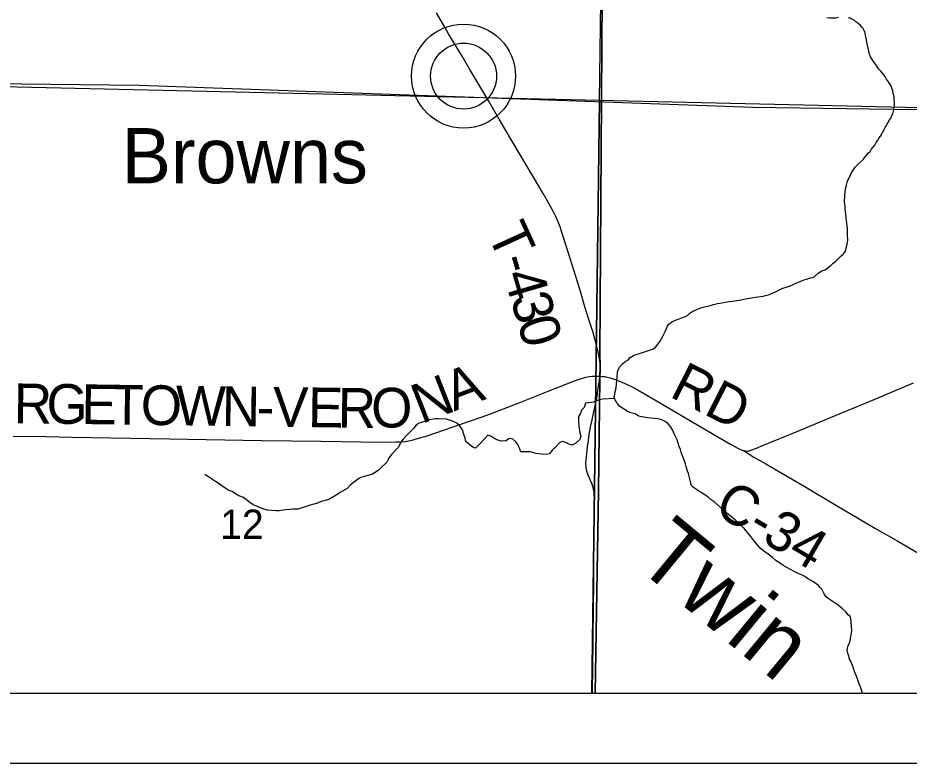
# Model space of a CAD drawing. Extents: x 0 to 1391, y -24 to 440.
# Drawn here: x 285.85 to 311.35, y 280 to 301.31 of the extents above; entities that cross this region are included whole.
import ezdxf

# ---------------------------------------------------------------- set-up
doc = ezdxf.new("R2010")
doc.units = 0
for name, color, linetype in [('GM_X_Corporation', 7, 'Continuous'), ('GM_X_County_Road', 7, 'Continuous'), ('GM_X_County_Road_Text', 7, 'Continuous'), ('GM_X_Major_River', 7, 'Continuous'), ('GM_X_Major_River_Text', 7, 'Continuous'), ('GM_X_Minor_River', 7, 'Continuous'), ('GM_X_Rail_Line', 7, 'Continuous'), ('GM_X_Section_Text', 7, 'Continuous'), ('GM_X_Township_Road', 7, 'Continuous'), ('GM_X_Township_Road_Text', 7, 'Continuous'), ('GM_X_Unincorporated', 7, 'Continuous'), ('GM_X_Unincorporated_Location', 7, 'Continuous'), ('GM_X_Unincorporated_Text', 7, 'Continuous'), ('SH_Data', 7, 'Continuous')]:
    doc.layers.add(name, color=color, linetype=linetype)

msp = doc.modelspace()

# ---------------------------------------------------------------- linework, layer by layer
at = {"layer": 'GM_X_Corporation'}
for points in [[(192, 321.564), (192, 282), (328, 282), (328, 319.315), (327.358, 319.321), (326.017, 319.331), (324.492, 319.344), (323.626, 319.346), (322.004, 319.36), (321.681, 319.364), (321.557, 319.363), (320.47, 319.355), (320.375, 319.355), (320.324, 319.361), (320.28, 319.374), (320.232, 319.401), (302.742, 319.575), (282.759, 319.815), (282.746, 319.815), (270.99, 319.899)], [(192, 321.564), (192, 282), (302.362, 282), (302.463, 287.791), (302.504, 290.987), (302.506, 291.392), (302.503, 291.694), (302.611, 309.266), (302.645, 314.81), (302.659, 314.843), (302.674, 314.915), (302.675, 315.033), (302.678, 315.834), (302.714, 317.94), (302.717, 318.152), (302.742, 319.575), (282.759, 319.815), (282.746, 319.815), (270.99, 319.899)], [(320.232, 319.401), (302.742, 319.575), (302.717, 318.152), (302.714, 317.94), (302.678, 315.834), (302.675, 315.033), (302.674, 314.915), (302.659, 314.843), (302.645, 314.81), (302.611, 309.266), (302.503, 291.694), (302.506, 291.392), (302.504, 290.987), (302.463, 287.791), (302.362, 282), (328, 282)]]:
    msp.add_lwpolyline(points, dxfattribs=at)
for points in [[(302.763, 319.503), (320.178, 319.362), (321.546, 319.363), (321.247, 298.517), (302.49, 298.953)], [(282.118, 282), (302.27, 282), (302.49, 298.953), (282.483, 299.41)], [(302.27, 282), (320.971, 282), (321.247, 298.517), (302.49, 298.953)]]:
    msp.add_lwpolyline(points, close=True, dxfattribs=at)
at = {"layer": 'GM_X_County_Road'}
for points in [[(285.718, 289.35), (286.662, 289.343), (287.395, 289.326), (290.191, 289.278), (292.825, 289.229), (294.527, 289.203), (295.658, 289.185), (296.292, 289.183), (296.665, 289.187), (296.815, 289.193), (296.927, 289.202), (297.022, 289.214), (297.104, 289.231), (297.19, 289.252), (297.282, 289.28), (297.556, 289.363), (298.523, 289.689), (299.323, 289.968), (300.16, 290.295), (301.021, 290.636), (301.819, 290.948), (301.976, 291.003), (302.096, 291.037), (302.205, 291.053), (302.279, 291.062), (302.356, 291.064), (302.503, 291.062)], [(302.503, 291.062), (302.566, 291.06), (302.639, 291.053), (302.676, 291.046)], [(302.676, 291.046), (302.712, 291.04), (302.797, 291.019), (302.884, 290.99), (302.967, 290.961), (303.039, 290.933), (303.131, 290.897), (303.284, 290.829), (303.479, 290.73), (304.076, 290.394), (305.875, 289.335), (306.239, 289.12), (306.325, 289.071), (306.444, 289.005), (306.545, 288.96), (306.597, 288.94), (306.625, 288.934)], [(306.625, 288.934), (306.662, 288.927), (306.704, 288.923), (306.746, 288.928), (306.783, 288.933), (306.823, 288.947), (306.98, 289.012), (307.197, 289.107), (307.394, 289.183), (308.21, 289.517), (309.095, 289.883), (310.348, 290.396), (311.47, 290.871)], [(306.625, 288.934), (306.773, 288.834), (306.909, 288.75), (307.248, 288.557), (308.341, 287.917), (309.272, 287.366), (310.383, 286.708), (311.02, 286.344), (311.708, 285.945)]]:
    msp.add_lwpolyline(points, dxfattribs=at)
at = {"layer": 'GM_X_Major_River'}
for points in [[(309.32, 301.319), (309.251, 301.305), (309.168, 301.306), (309.077, 301.308), (308.994, 301.317)], [(309.248, 294.357), (309.401, 294.506), (309.47, 294.566), (309.509, 294.611), (309.533, 294.664), (309.549, 294.739), (309.573, 294.838), (309.59, 294.959), (309.585, 295.111), (309.588, 295.278), (309.568, 295.438), (309.548, 295.59), (309.535, 295.719), (309.522, 295.833), (309.516, 295.94), (309.503, 296.046), (309.506, 296.236), (309.515, 296.335), (309.532, 296.425), (309.556, 296.531), (309.589, 296.645), (309.628, 296.743), (309.667, 296.818), (309.706, 296.901), (309.753, 296.969), (309.8, 297.044), (309.861, 297.096), (309.915, 297.156), (310.038, 297.276), (310.092, 297.335), (310.138, 297.395), (310.184, 297.448), (310.23, 297.493), (310.262, 297.545), (310.308, 297.605), (310.362, 297.673), (310.409, 297.748), (310.455, 297.816), (310.494, 297.883), (310.533, 297.928), (310.634, 298.124), (310.665, 298.177), (310.704, 298.245), (310.736, 298.313), (310.79, 298.395), (310.829, 298.455), (310.845, 298.501), (310.884, 298.568), (310.9, 298.644), (310.926, 298.811), (310.927, 298.879), (310.921, 298.963), (310.915, 299.054), (310.894, 299.153), (310.88, 299.237), (310.851, 299.298), (310.829, 299.359), (310.756, 299.482), (310.704, 299.558), (310.66, 299.635), (310.541, 299.789), (310.475, 299.858), (310.416, 299.95), (310.349, 300.035), (310.246, 300.196), (310.217, 300.272), (310.196, 300.356), (310.174, 300.448), (310.161, 300.531), (310.139, 300.615), (310.125, 300.684), (310.112, 300.768), (310.098, 300.821), (310.091, 300.867), (310.077, 300.92), (310.054, 300.958), (310.04, 300.997), (309.996, 301.05), (309.959, 301.097), (309.876, 301.159), (309.824, 301.197), (309.772, 301.244), (309.712, 301.275), (309.66, 301.306), (309.599, 301.315)], [(304.708, 289.242), (304.671, 289.326), (304.628, 289.418), (304.584, 289.517), (304.518, 289.624), (304.451, 289.701), (304.369, 289.771), (304.294, 289.81), (304.234, 289.826), (304.158, 289.843), (304.076, 289.859), (303.962, 289.869), (303.849, 289.878), (303.608, 289.927), (303.533, 289.982), (303.473, 289.998), (303.39, 290.022), (303.277, 290.062), (303.173, 290.132), (303.076, 290.201), (303.009, 290.278), (302.965, 290.34), (302.935, 290.386), (302.921, 290.424), (302.914, 290.477), (302.93, 290.545), (302.939, 290.629), (302.964, 290.735), (302.98, 290.833), (302.99, 290.939), (302.999, 291.038), (303.001, 291.175), (303.01, 291.22), (303.064, 291.325), (303.149, 291.415), (303.226, 291.482), (303.287, 291.527), (303.325, 291.557), (303.371, 291.602), (303.417, 291.624), (303.463, 291.653), (303.539, 291.683), (303.63, 291.711), (303.752, 291.755), (303.98, 291.827), (304.064, 291.857), (304.141, 291.954), (304.218, 292.059), (304.296, 292.195), (304.375, 292.36), (304.438, 292.496), (304.476, 292.556), (304.561, 292.623), (304.667, 292.667), (304.766, 292.704), (304.865, 292.74), (304.949, 292.777), (305.018, 292.813), (305.079, 292.866), (305.163, 292.925), (305.27, 292.977), (305.361, 293.013), (305.46, 293.042), (305.657, 293.084), (305.756, 293.113), (305.87, 293.142), (305.991, 293.163), (306.097, 293.184), (306.196, 293.197), (306.287, 293.211), (306.363, 293.225), (306.545, 293.253), (306.659, 293.274), (306.787, 293.294), (306.947, 293.322), (307.174, 293.357), (307.242, 293.371), (307.288, 293.378), (307.326, 293.392), (307.372, 293.414), (307.562, 293.495), (307.646, 293.547), (307.737, 293.583), (307.798, 293.605), (307.89, 293.634), (307.927, 293.641), (308.049, 293.7), (308.179, 293.759), (308.316, 293.81), (308.437, 293.846), (308.529, 293.882), (308.597, 293.889), (308.635, 293.911), (308.743, 294.008), (308.85, 294.074), (308.941, 294.111), (308.987, 294.133), (309.056, 294.2), (309.117, 294.245), (309.171, 294.297), (309.248, 294.357)], [(310.019, 282), (310.008, 282.028), (309.965, 282.15), (309.921, 282.272), (309.878, 282.387), (309.842, 282.486), (309.805, 282.57), (309.776, 282.647), (309.748, 282.746), (309.712, 282.837), (309.675, 282.922), (309.646, 282.975), (309.631, 283.021), (309.625, 283.059), (309.603, 283.12), (309.574, 283.227), (309.591, 283.34), (309.638, 283.438), (309.662, 283.506), (309.671, 283.552), (309.68, 283.635), (309.696, 283.711), (309.705, 283.802), (309.68, 284.136), (309.659, 284.19), (309.614, 284.229), (309.54, 284.328), (309.443, 284.413), (309.316, 284.522), (309.174, 284.615), (309.062, 284.693), (308.987, 284.747), (308.95, 284.793), (308.921, 284.839), (308.855, 284.977), (308.803, 285.023), (308.751, 285.085), (308.692, 285.132), (308.609, 285.186), (308.445, 285.28), (308.362, 285.334), (308.272, 285.381), (308.175, 285.428), (308.062, 285.483), (307.957, 285.538), (307.845, 285.593), (307.74, 285.655), (307.635, 285.725), (307.538, 285.795), (307.426, 285.888), (307.314, 285.973), (307.195, 286.059), (307.091, 286.152), (306.994, 286.259), (306.905, 286.367), (306.816, 286.482), (306.639, 286.698), (306.557, 286.79), (306.46, 286.883), (306.371, 286.96), (306.192, 287.1), (306.11, 287.169), (306.02, 287.247), (305.938, 287.316), (305.856, 287.401), (305.767, 287.471), (305.685, 287.533), (305.595, 287.603), (305.416, 287.727), (305.334, 287.782), (305.266, 287.828), (305.206, 287.867), (305.162, 287.898), (305.125, 287.944), (305.103, 288.005), (305.089, 288.059), (305.075, 288.127), (305.053, 288.211), (305.032, 288.287), (305.01, 288.349), (304.967, 288.486), (304.946, 288.562), (304.917, 288.646), (304.888, 288.738), (304.859, 288.807), (304.83, 288.891), (304.809, 288.974), (304.773, 289.058), (304.744, 289.15), (304.708, 289.242)]]:
    msp.add_lwpolyline(points, dxfattribs=at)
at = {"layer": 'GM_X_Minor_River'}
for points in [[(302.921, 290.424), (302.59, 290.411), (302.484, 290.391), (302.407, 290.362), (302.315, 290.327), (302.086, 290.294), (302.053, 290.174), (301.975, 290.092), (301.942, 289.994), (301.894, 289.912), (301.892, 289.829), (301.895, 289.639), (301.928, 289.448), (301.956, 289.341), (301.931, 289.251), (301.814, 289.155), (301.707, 289.097), (301.616, 289.122), (301.526, 289.17), (301.428, 289.195), (301.352, 289.174), (301.234, 289.033), (301.134, 288.952), (301.063, 288.847), (300.978, 288.827), (300.842, 288.838), (300.751, 288.848), (300.676, 288.857), (300.51, 288.907), (300.335, 288.904), (300.237, 288.907), (300.194, 289.029), (300.151, 289.114), (300.1, 289.191), (300.01, 289.269), (299.912, 289.287), (299.812, 289.221), (299.682, 289.209), (299.584, 289.235), (299.494, 289.275), (299.382, 289.354), (299.3, 289.379), (299.214, 289.282), (299.042, 289.104), (298.941, 289.008), (298.866, 289.04), (298.739, 289.127), (298.665, 289.197), (298.644, 289.289), (298.602, 289.427), (298.575, 289.534), (298.487, 289.658), (298.413, 289.72), (298.27, 289.792), (298.195, 289.809), (298.112, 289.834), (297.884, 289.848), (297.778, 289.85), (297.694, 289.83), (297.565, 289.818), (297.48, 289.774), (297.327, 289.718), (297.25, 289.666), (297.171, 289.57), (296.953, 289.355), (296.867, 289.258), (296.804, 289.169), (296.732, 289.027), (296.537, 288.826), (296.467, 288.73), (296.426, 288.639), (296.348, 288.55), (296.255, 288.462), (296.154, 288.365), (295.992, 288.263), (295.9, 288.235), (295.793, 288.208), (295.663, 288.173), (295.57, 288.107), (295.485, 288.048), (295.353, 287.945), (295.275, 287.856), (295.075, 287.74), (294.959, 287.659), (294.743, 287.543), (294.644, 287.508), (294.529, 287.481), (294.422, 287.43), (294.322, 287.402), (294.177, 287.368), (294.07, 287.333), (293.978, 287.297), (293.871, 287.262), (293.704, 287.259), (293.627, 287.253), (293.513, 287.241), (293.33, 287.215), (293.239, 287.217), (293.118, 287.228), (292.989, 287.239), (292.884, 287.264)], [(292.884, 287.264), (292.764, 287.313), (292.688, 287.345), (292.583, 287.386), (292.456, 287.473), (292.382, 287.535), (292.308, 287.598), (292.172, 287.647), (292.075, 287.703), (291.978, 287.766), (291.888, 287.799), (291.798, 287.854), (291.723, 287.902), (291.582, 288.004), (291.507, 288.059), (291.417, 288.114), (291.305, 288.186), (291.201, 288.257)]]:
    msp.add_lwpolyline(points, dxfattribs=at)
at = {"layer": 'GM_X_Rail_Line'}
msp.add_lwpolyline([(272.571, 299.576), (275.01, 299.553), (289.325, 299.383), (306.874, 298.762), (316.291, 298.625), (324.811, 298.433), (325.847, 298.317), (326.715, 298.164), (327.827, 297.823), (328, 297.733)], dxfattribs=at)
at = {"layer": 'GM_X_Township_Road'}
for points in [[(302.416, 291.897), (302.395, 291.993), (302.299, 292.34), (302.197, 292.661), (302.075, 293.052), (301.928, 293.553), (301.536, 294.796), (301.445, 295.093), (301.362, 295.339), (301.299, 295.501), (301.238, 295.636), (301.183, 295.746), (300.991, 296.093), (300.878, 296.287), (300.602, 296.758), (300.333, 297.206), (300.034, 297.722), (299.624, 298.418), (299.333, 298.91), (299.069, 299.359), (298.784, 299.84), (298.566, 300.216), (298.384, 300.513), (298.175, 300.852), (298.075, 301.023), (297.829, 301.455)], [(302.503, 291.062), (302.514, 291.161), (302.519, 291.209), (302.521, 291.267), (302.518, 291.351), (302.511, 291.438), (302.489, 291.567), (302.438, 291.802), (302.416, 291.897)], [(302.377, 290.273), (302.419, 290.496), (302.447, 290.667), (302.468, 290.834), (302.486, 290.952), (302.503, 291.062)], [(302.298, 287.914), (302.278, 287.978), (302.236, 288.08), (302.164, 288.239), (302.133, 288.322), (302.117, 288.384), (302.107, 288.447), (302.102, 288.573), (302.106, 288.673), (302.125, 288.847), (302.151, 289.044), (302.174, 289.229), (302.197, 289.402), (302.213, 289.5), (302.235, 289.622), (302.278, 289.816), (302.359, 290.179), (302.377, 290.273)], [(302.335, 287.732), (302.328, 287.79), (302.307, 287.885), (302.298, 287.914)], [(302.29, 282), (302.291, 282.079), (302.304, 282.716), (302.311, 283.507), (302.32, 284.479), (302.329, 285.11), (302.331, 285.83), (302.334, 286.701), (302.346, 287.26), (302.347, 287.57), (302.34, 287.693), (302.335, 287.732)]]:
    msp.add_lwpolyline(points, dxfattribs=at)
at = {"layer": 'GM_X_Unincorporated'}
for radius in [1.488, 0.943]:
    msp.add_circle((298.601, 299.646), radius, dxfattribs=at)
at = {"layer": 'GM_X_Unincorporated_Location'}
msp.add_line((298.601, 299.646), (298.601, 299.646), dxfattribs=at)
at = {"layer": 'SH_Data'}
for p, q in [((192, 282), (328, 282)), ((190, 280), (330, 280)), ((190, 280), (330, 280))]:
    msp.add_line(p, q, dxfattribs=at)

# ---------------------------------------------------------------- texts
at = {"layer": 'GM_X_County_Road_Text'}
for s, height, rotation, p in [('RD', 1.1364, 332.997, (304.459, 290.496)), ('A', 1.136, 20.8571, (298.326, 290.056)), ('N', 1.136, 21.4335, (297.398, 289.692)), ('R', 1.136, 359.2278, (285.728, 289.724)), ('G', 1.136, 359.2241, (286.662, 289.711)), ('E', 1.136, 359.2292, (287.662, 289.698)), ('T', 1.136, 359.2243, (288.511, 289.686)), ('O', 1.136, 359.2258, (289.361, 289.675)), ('W', 1.136, 359.2283, (290.361, 289.661)), ('N', 1.136, 359.2241, (291.678, 289.643)), ('V', 1.136, 359.2241, (293.144, 289.623)), ('E', 1.136, 359.2292, (294.144, 289.61)), ('R', 1.136, 359.2759, (294.995, 289.598)), ('O', 1.136, 1.1032, (295.968, 289.587)), ('-', 1.136, 359.2289, (292.678, 289.63)), ('C-34', 1.1364, 329.448, (305.719, 287.165))]:
    msp.add_text(s, height=height, rotation=rotation, dxfattribs=at).set_placement(p)
at = {"layer": 'GM_X_Major_River_Text'}
msp.add_text('Twin', height=1.8935, rotation=320.4268, dxfattribs=at).set_placement((303.449, 285.682))
at = {"layer": 'GM_X_Section_Text'}
msp.add_text('12', height=0.8371, rotation=0, dxfattribs=at).set_placement((291.639, 286.414))
at = {"layer": 'GM_X_Township_Road_Text'}
for s, rotation, p in [('T', 294.627, (299.264, 295.144)), ('-', 286.6821, (299.604, 294.41)), ('4', 286.315, (299.737, 293.965)), ('3', 286.1634, (299.934, 293.294)), ('0', 286.1205, (300.128, 292.622))]:
    msp.add_text(s, height=1.136, rotation=rotation, dxfattribs=at).set_placement(p)
at = {"layer": 'GM_X_Unincorporated_Text'}
msp.add_text('Browns', height=1.5795, rotation=0, dxfattribs=at).set_placement((288.822, 296.581))

doc.saveas('drawing.dxf')
